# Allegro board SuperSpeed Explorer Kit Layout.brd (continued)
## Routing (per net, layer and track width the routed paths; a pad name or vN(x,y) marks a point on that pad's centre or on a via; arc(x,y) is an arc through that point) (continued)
DQ1: length 107.6
  TOP w0.183: R45.2 v2(51.3,39.51)
  L03_SIG1 w0.127: v2(51.3,39.51) 51.3,41.91 51.51,42.13 51.8,42.13 52.01,41.92 52.01,40.19 52.19,40.02 52.48,40.02 52.69,40.23 52.69,43.31 52.92,43.54 53.22,43.54 53.42,43.34 53.42,41.4 53.59,41.22 53.84,41.22 54.04,41.43 54.04,43.2 56.03,45.19 58.86,45.19 59.06,45.39 59.06,45.76 58.81,46 56.16,46 54.14,43.98 53.91,43.98 53.76,44.13 53.76,44.37 56.26,46.88 56.26,48.15 56.9,48.78 58.86,48.78 J6.36
  L06_SIG2 w0.127: v3(56.1,42.53) 56.03,42.53 55.6,42.97 55.6,44.05 56.58,45.03 60.74,45.03 61.84,46.14 66.61,46.14 67.52,45.23 74.93,45.23 75.18,45.48 75.18,46.29 74.69,46.78 67.83,46.78 67.5,47.11 67.5,47.83 67.78,48.12 73.43,48.12 74.08,48.76 74.08,51.28 73.79,51.58 73.23,51.58 73.1,51.45 73.1,50.52 72.89,50.31 72.53,50.31 72.3,50.53 72.3,51.49 72.04,51.75 64.44,51.75 64.11,51.42 64.11,49.45 63.7,49.05 61.7,49.05 61.47,49.28 61.47,51.96 61.09,52.34 59.18,52.34 58.93,52.08 58.93,50.31 59.12,50.12 J6.36
  BOTTOM w0.183: U5.B7 v3(56.1,42.53)
DQ2: length 110
  TOP w0.183: R27.2 v2(39.51,42.95)
  L06_SIG2 w0.127: v2(39.51,42.95) 38.94,43.52 36.21,43.52 33.5,46.24 31.97,46.24 30.99,47.22 30.99,50.41 31.78,51.2 56.58,51.2 J6.34 57.66,49 58,48.65 65.55,48.65 66.39,49.49 66.39,51.12 66.6,51.32 67.03,51.32 67.21,51.14 67.21,50.35 67.41,50.15 67.94,50.15 68.14,50.35 68.14,51.08 68.37,51.32 68.94,51.32 69.15,51.1 69.15,50.34 69.39,50.11 69.9,50.11 70.12,50.34 70.12,51.07 70.37,51.32 71.5,51.32 71.7,51.12 71.7,49.9 71.48,49.69 67.24,49.69 67.11,49.55 67.11,49.26 67.26,49.11 71.65,49.11 71.81,48.96 71.81,48.72 71.67,48.58 67.66,48.58 67.12,48.03 67.12,46.95 67.69,46.38 72.89,46.38 73.05,46.22 73.05,45.95 72.88,45.79 67.57,45.79 66.81,46.55 61.63,46.55 60.62,45.54 56.37,45.54 55.21,44.37 55.21,42.16 v3(56.1,41.26)
  BOTTOM w0.183: 56.58,40.78 v3(56.1,41.26)
DQ3: length 111.2
  TOP w0.183: R47.2 v2(51.18,36.72)
  L03_SIG1 w0.127: v2(51.18,36.72) 52.39,37.92 52.84,37.92 53.17,37.59 53.17,30.28 52.91,30.02 52.59,30.02 52.31,30.31 52.31,35.86 52.07,36.09 51.68,36.09 51.45,35.86 51.45,33.48 51.21,33.23 50.9,33.23 50.67,33.46 50.67,35.97 50.12,36.53 50.12,42.54 53.78,46.2 53.78,49.74 54.16,50.12 55.12,50.12
  L06_SIG2 w0.127: 55.12,50.12 55.01,50.22 54.03,50.22 53.72,49.92 53.72,49.22 54.1,48.85 55.93,48.85 56.32,48.45 56.32,46.84 56.59,46.57 60.3,46.57 60.48,46.39 60.48,46.13 60.33,45.98 55.15,45.98 54.82,45.65 54.82,40.88 55.07,40.63 56.5,40.63 56.73,40.86 56.73,43.21 57.12,43.6 60.54,43.6 62.27,45.34 66.25,45.34 68.78,42.81 71.25,42.81 71.71,42.34 71.71,40.58 71.47,40.33 71.05,40.33 70.84,40.55 70.84,42.01 70.65,42.19 67.41,42.19 66.94,42.66 66.94,43.64 65.67,44.91 62.51,44.91 60.75,43.15 58.12,43.15 57.85,42.89 57.85,40.84 57.52,40.51 57.12,40.51 56.61,39.99 v3(56.1,39.99)
  BOTTOM w0.183: U5.D7 v3(56.1,39.99)
DQ4: length 102
  TOP w0.183: v2(47.12,41.16) 45.85,41.16 45.1,40.41 R32.2
  L06_SIG2 w0.127: v3(56.1,38.72) 56.5,38.72 57.32,37.9 59.8,37.9 60.74,38.84 60.74,42.41 60.41,42.74 59.49,42.74 59.22,42.46 59.22,38.59 58.89,38.27 58.34,38.27 58.12,38.49 58.12,39.07 57.87,39.33 55.56,39.33 55.08,38.85 55.08,36.83 54.91,36.66 54.52,36.66 54.36,36.82 54.36,41.04 54.18,41.23 53.95,41.23 53.82,41.09 53.82,38.12 53.6,37.9 53.28,37.9 53.07,38.11 53.07,40.76 52.85,40.97 52.09,40.97 51.9,41.16 51.9,41.59 52.03,41.72 54.19,41.72 54.32,41.84 54.32,42.1 54.19,42.22 52.03,42.22 51.9,42.35 51.9,42.6 52.03,42.73 54.19,42.73 54.32,42.86 54.32,43.11 54.19,43.24 52.03,43.24 51.9,43.37 51.9,43.62 52.03,43.75 54.19,43.75 54.32,43.87 54.32,44.13 54.19,44.26 52.03,44.26 51.9,44.38 51.9,44.64 52.03,44.76 54.19,44.76 54.32,44.89 54.32,45.14 54.19,45.27 52.03,45.27 51.9,45.4 51.9,46.16 52.19,46.45 53.81,46.45 54.03,46.67 54.03,47.84 53.14,48.73 51.44,48.73 51.23,48.95 51.23,49.69 51.65,50.12 52.58,50.12
  BOTTOM w0.183: 56.58,38.24 v3(56.1,38.72) ; 52.58,50.12 53.39,50.12 54.63,48.87 58.28,48.87 58.85,49.43 58.85,50.66 58.28,51.22 51.68,51.22 51.33,50.87 51.33,49.6 50.37,48.64 46.74,48.64 46.23,48.13 46.23,42.05 v2(47.12,41.16)
DQ5: length 110.3
  TOP w0.183: R30.2 v2(47.42,42.95)
  L03_SIG1 w0.127: v2(47.42,42.95) 47.81,42.56 47.81,40.84 47.45,40.49 46.88,40.49 46.57,40.8 46.57,43.31 46.97,43.71 48.09,43.71 50.24,45.86 50.87,45.86 51.26,45.47 51.53,45.47 51.79,45.73 51.79,46.07 51.35,46.51 50.13,46.51 47.96,44.34 46.73,44.34 46.57,44.5 46.57,44.89 46.75,45.07 48.01,45.07 49.33,46.39 49.33,46.65 49.24,46.75 49,46.75 47.76,45.51 46.74,45.51 46.59,45.65 46.59,45.93 46.76,46.1 47.72,46.1 48.72,47.09 48.72,48.11 49.36,48.75 51.06,48.75 51.38,49.07 51.38,49.85 51.12,50.12 50.04,50.12
  L06_SIG2 w0.127: 50.04,50.12 49.02,50.12 48.71,49.82 48.71,46.67 51.5,43.89 51.5,40.9 52.65,39.74 52.65,37.95 54.45,36.16 55.25,36.16 55.55,36.45 55.55,37.65 55.79,37.89 56.46,37.89 56.72,37.63 56.72,37.2 56.95,36.97 60.21,36.97 60.46,37.22 60.46,37.6 61.19,38.33 61.19,42.61 61.35,42.77 61.52,42.77 61.68,42.61 61.68,38.29 61.9,38.07 62.59,38.07 62.85,38.33 62.85,39.04 63.07,39.26 63.9,39.26 64.17,39 64.17,38.15 63.97,37.95 63.17,37.95 62.89,37.68 62.89,37.04 63.09,36.85 63.88,36.85 64.17,36.56 64.17,33.28 64,33.11 63.27,33.11 63.14,32.98 63.14,32.3 63.28,32.16 63.95,32.16 64.19,31.92 64.19,30.91 63.92,30.64 63.07,30.64 62.78,30.93 62.78,36.33 62.47,36.63 61.79,36.63 61.64,36.78 61.64,37.42 61.46,37.61 61,37.61 60.84,37.45 60.84,36.86 60.62,36.63 56.41,36.63 56.1,36.95 v3(56.1,37.45)
  BOTTOM w0.183: U5.F7 v3(56.1,37.45)
DQ6: length 112.3
  TOP w0.183: R48.2 v2(49.53,35.32)
  L03_SIG1 w0.127: v2(49.53,35.32) 49.53,34.78 49.33,34.58 49.09,34.58 48.91,34.76 48.91,42.69 50.8,44.58 50.8,44.94 50.54,45.2 50.2,45.2 48.24,43.24 48.24,34.41 48.11,34.28 47.79,34.28 47.65,34.43 47.65,39.67 47.23,40.09 46.47,40.09 46.13,40.42 46.13,49.78 46.47,50.12 47.5,50.12
  L06_SIG2 w0.127: 47.5,50.12 46.48,50.12 46.12,49.76 46.12,46.97 45.72,46.56 44.88,46.56 44.42,46.1 41.81,46.1 41.49,45.78 41.49,45.52 41.85,45.16 44.27,45.16 45.22,46.11 48.66,46.11 51.08,43.7 51.08,40.57 52.26,39.39 52.26,37.77 54.11,35.92 54.11,33.37 54.27,33.21 54.45,33.21 54.63,33.38 54.63,35.62 54.75,35.74 55.04,35.74 55.15,35.63 55.15,32.23 55.28,32.09 55.48,32.09 55.63,32.24 55.63,35.09 55.9,35.36 57.57,35.36 57.82,35.11 57.82,33.33 58.01,33.14 60.66,33.14 61.81,31.98 62.15,31.98 62.36,32.2 62.36,32.46 61.69,33.14 61.69,35.6 61.53,35.76 61.28,35.76 61.14,35.62 61.14,33.69 61.01,33.57 60.72,33.57 60.56,33.72 60.56,35.15 60.27,35.44 59.72,35.44 59.44,35.17 59.44,34.38 59.23,34.17 58.36,34.17 58.18,34.35 58.18,35.49 57.95,35.72 56.56,35.72 v3(56.1,36.18)
  BOTTOM w0.183: 56.58,35.7 v3(56.1,36.18)
DQ7: length 99.8
  TOP w0.183: R34.2 v2(45.85,36.72)
  L06_SIG2 w0.127: 44.96,50.12 43.94,50.12 43.72,49.9 43.72,46.82 43.46,46.56 41.34,46.56 40.92,46.14 40.92,45.5 41.68,44.74 44.46,44.74 45.45,45.73 48.5,45.73 50.68,43.56 50.68,39.22 51.09,38.8 51.52,38.8 51.83,38.49 51.83,37.6 53.65,35.77 53.65,33.26 54.59,32.32 54.59,32.31 54.59,30 54.73,29.86 54.96,29.86 55.12,30.02 55.12,31.11 56.33,32.32 60.31,32.32 61.28,31.35 61.28,25.96 61.6,25.64 63.8,25.64 64.11,25.96 64.11,29.22 63.8,29.53 62.01,29.53 61.63,29.91 61.63,31.58 60.46,32.74 56.89,32.74 56.56,33.06 56.56,34.45 v3(56.1,34.91)
  BOTTOM w0.183: v2(45.85,36.72) 45.72,36.72 45.09,37.35 45.09,41.95 43.87,43.17 43.87,43.71 44.11,43.96 44.92,43.96 45.11,44.14 45.11,44.51 44.92,44.69 44.11,44.69 43.93,44.87 43.93,45.24 44.11,45.42 44.92,45.42 45.11,45.6 45.11,45.97 44.92,46.15 44.11,46.15 43.93,46.33 43.93,51.13 44.18,51.38 48.18,51.38 48.78,50.78 48.78,49.31 48.5,49.03 45.21,49.03 44.97,49.27 44.97,50.1 44.96,50.12 ; U5.H7 v3(56.1,34.91)
DQ8: length 113.3
  TOP w0.183: R49.2 v2(49.53,33.92)
  L03_SIG1 w0.127: v2(49.53,33.92) 49.18,33.57 47.64,33.57 47.17,34.03 47.17,38.33 46.87,38.63 46.11,38.63 45.75,38.99 45.75,40.26 45.75,40.26 45.75,45.99 45.35,46.38 45.1,46.38 44.87,46.16 44.87,42.64 44.67,42.44 44.43,42.44 44.23,42.63 44.23,46.12 44.06,46.3 43.8,46.3 43.65,46.15 43.65,43.83 43.43,43.62 43.23,43.62 43.04,43.81 43.04,45.6 42.85,45.79 38.8,45.79 38.61,45.98 38.61,46.29 38.84,46.52 43.37,46.52 43.67,46.81 43.67,48.84 42.42,50.08 J6.22
  L06_SIG2 w0.127: J6.22 41.53,50.12 41.06,49.66 41.06,46.99 40.58,46.51 37.16,46.51 36.94,46.29 36.94,46.03 37.13,45.83 39.98,45.83 41.53,44.28 44.7,44.28 45.74,45.32 48.31,45.32 50.25,43.38 50.25,38.45 53.2,35.51 53.2,33.15 54.17,32.18 54.17,29.84 54.59,29.42 55.36,29.42 55.56,29.63 55.56,30.43 55.86,30.73 57.74,30.73 58.01,30.47 58.01,29.64 58.29,29.36 59.23,29.36 59.46,29.6 59.46,30.6 59.65,30.79 60.09,30.79 60.36,30.51 60.36,24.49 60.48,24.37 60.77,24.37 60.89,24.49 60.89,31.17 60.15,31.9 56.59,31.9 v3(56.1,31.41)
  BOTTOM w0.183: U5.K7 v3(56.1,31.41)
DQ9: length 101.2
  TOP w0.183: R37.2 v2(45.85,32.53)
  L06_SIG2 w0.127: J6.20 39.88,49.27 39.52,48.91 36.77,48.91 36.25,48.39 36.25,46.04 36.89,45.4 39.74,45.4 41.27,43.87 44.9,43.87 45.95,44.91 48.11,44.91 49.87,43.15 49.87,36.59 50.42,36.04 50.42,30.58 50.59,30.41 51.02,30.41 51.18,30.57 51.18,35.91 51.32,36.04 51.57,36.04 51.69,35.92 51.69,30.54 51.82,30.41 52.07,30.41 52.2,30.54 52.2,35.37 52.32,35.49 52.57,35.49 52.71,35.35 52.71,30.54 52.84,30.41 53.09,30.41 53.22,30.54 53.22,32.04 53.35,32.17 53.6,32.17 53.72,32.05 53.72,29.51 54.53,28.71 55.24,28.71 56.1,29.57 v3(56.1,30.14)
  BOTTOM w0.183: v2(45.85,32.53) 45.85,32.98 46.02,33.16 47.09,33.16 47.37,33.44 47.37,35.73 47.02,36.08 45.47,36.08 44.53,37.02 44.53,41.62 43.45,42.7 43.45,43.4 43.1,43.75 42.06,43.75 41.85,43.95 41.85,44.39 42.04,44.58 43.19,44.58 43.45,44.83 43.45,45.21 43.27,45.39 42.09,45.39 41.82,45.65 41.82,46.17 42.05,46.39 43.03,46.39 43.45,46.81 43.45,50.82 42.98,51.29 40.17,51.29 39.88,51 J6.20 ; 56.58,30.62 v3(56.1,30.14)
DQ10: length 99
  TOP w0.183: R35.2 v2(45.85,35.32)
  L06_SIG2 w0.127: 37.34,50.12 36.29,50.12 35.86,49.68 35.86,45.8 36.7,44.95 39.52,44.95 41.01,43.47 45.17,43.47 46.21,44.5 47.85,44.5 49.46,42.89 49.46,36.32 50.04,35.74 50.04,30.27 50.35,29.95 52.74,29.95 54.46,28.23 57.4,28.23 57.83,27.8 57.83,26.5 59.25,25.08 59.25,22.74 59.52,22.46 61.42,22.46 61.94,22.98 63.75,22.98 63.99,23.22 63.99,24.06 63.76,24.29 61.6,24.29 60.98,23.67 60.14,23.67 59.79,24.02 59.79,25.67 59.26,26.2 59.26,28.09 59.01,28.33 58.11,28.33 57.9,28.54 57.9,28.98 57.56,29.32 56.54,29.32 v3(56.1,28.87)
  BOTTOM w0.183: v2(45.85,35.32) 45.47,35.32 44.02,36.77 44.02,40.63 41.35,43.3 41.35,44.38 41.12,44.61 40.04,44.61 39.8,44.85 39.8,45.29 40.08,45.58 40.86,45.58 41.39,46.1 41.39,48.54 40.89,49.04 36.49,49.04 36.01,49.52 36.01,50.96 36.35,51.3 38.34,51.3 38.63,51 38.63,50.28 38.39,50.03 37.42,50.03 37.34,50.12 ; U5.M7 v3(56.1,28.87)
DQ11: length 116.2
  TOP w0.183: R51.2 v2(49.53,31.13)
  L03_SIG1 w0.127: v2(49.53,31.13) 49.42,31.13 48.03,29.74 48.03,28.41 47.41,27.79 45.15,27.79 44.55,28.39 44.55,40.42 40.5,44.48 35.39,44.48 34.28,45.59 29.13,45.59 28.94,45.78 28.94,46.27 29.19,46.52 30.76,46.52 31.03,46.79 31.03,48.65 31.25,48.87 34.69,48.87 35.01,49.19 35.01,49.9 34.8,50.12
  L06_SIG2 w0.127: 34.8,50.12 34.03,50.12 33.66,49.74 33.66,47.26 36.51,44.4 39.42,44.4 40.77,43.05 45.38,43.05 46.32,43.99 47.75,43.99 48.93,42.81 48.93,29.46 49.22,29.17 51.5,29.17 51.68,28.98 51.68,28.77 51.5,28.58 49.1,28.58 48.93,28.41 48.93,26.89 49.1,26.71 49.36,26.71 49.55,26.9 49.55,27.98 49.69,28.12 50.65,28.12 50.78,27.99 50.78,26.59 50.9,26.46 51.16,26.46 51.29,26.59 51.29,27.95 51.42,28.09 51.85,28.09 51.97,27.97 51.97,26.03 52.1,25.9 52.35,25.9 52.48,26.03 52.48,27.47 52.61,27.6 52.86,27.6 52.99,27.47 52.99,26.03 53.11,25.9 53.37,25.9 53.49,26.03 53.49,27.47 53.62,27.6 53.88,27.6 54,27.47 54,26.03 54.13,25.9 54.38,25.9 54.51,26.03 54.51,27.47 54.64,27.6 54.89,27.6 55.02,27.47 55.02,26.03 55.15,25.9 55.4,25.9 55.53,26.03 55.53,26.62 55.77,26.86 56.42,26.86 56.58,27.03 56.58,27.45 56.43,27.6 56.1,27.6 v3(56.1,27.6)
  BOTTOM w0.183: 56.58,28.08 v3(56.1,27.6)
DQ12: length 102.2
  TOP w0.183: R36.2 v2(45.85,33.92)
  L06_SIG2 w0.127: v3(56.1,26.33) 56.65,26.33 57.11,25.87 57.57,25.87 58,25.44 58,23.27 57.74,23.02 56.94,23.02 56.64,23.32 56.64,25.27 56.39,25.52 52.72,25.52 52.52,25.33 52.52,24.98 52.73,24.77 53.72,24.77 53.9,24.59 53.9,24.22 53.7,24.01 52.35,24.01 51.36,23.03 51.09,23.03 50.94,23.18 50.94,23.35 51.6,24.01 51.6,24.19 51.44,24.36 51.2,24.36 50.47,23.63 48.81,23.63 48.52,23.92 48.52,24.4 48.77,24.65 50.99,24.65 51.15,24.81 51.15,25.14 50.96,25.34 48.87,25.34 48.52,25.69 48.52,42.62 47.62,43.53 46.43,43.53 45.54,42.63 40.62,42.63 39.23,44.02 36.26,44.02 33.27,47 33.27,49.1 32.26,50.12
  BOTTOM w0.183: U5.P7 v3(56.1,26.33) ; 32.26,50.12 32.23,50.09 30.99,50.09 30.78,50.29 30.78,51.06 31.04,51.32 33.19,51.32 33.44,51.08 33.44,49.47 33.82,49.09 35.68,49.09 36.11,48.65 40.51,48.65 40.91,48.26 40.91,46.81 40.21,46.12 39.4,46.12 39.08,45.8 39.08,44.94 43.51,40.5 43.51,36.26 v2(45.85,33.92)
DQ13: length 115
  TOP w0.183: R52.2 v2(49.53,29.73)
  L03_SIG1 w0.127: v2(49.53,29.73) 48.99,29.73 48.78,29.53 48.78,26.02 48.53,25.77 48.05,25.77 47.38,26.43 45.85,26.43 44.17,28.11 44.17,40.04 40.28,43.94 35.15,43.94 33.97,45.12 28.73,45.12 28.23,45.62 28.23,49.69 28.65,50.12 J6.12
  L06_SIG2 w0.127: v3(56.1,25.06) 55.72,25.06 55.34,24.68 55.34,23.72 55.13,23.5 52.51,23.5 51.6,22.59 50.59,22.59 49.93,23.25 49.33,23.25 48.84,22.76 48.4,22.76 48.08,23.08 48.08,41.57 46.94,42.72 46.32,42.72 45.78,42.18 37.56,42.18 36.82,41.44 35.75,41.44 35.43,41.75 35.43,43.77 33.66,45.54 23.52,45.54 23.33,45.74 23.33,46.17 23.58,46.42 28.14,46.42 28.41,46.69 28.41,49.71 28.82,50.12 J6.12
  BOTTOM w0.183: U5.R7 v3(56.1,25.06)
DQ14: length 119
  TOP w0.183: R38.2 v2(45.85,31.13)
  L06_SIG2 w0.127: v3(56.1,23.79) 55.3,22.99 52.67,22.99 51.81,22.13 48.18,22.13 47.63,22.68 47.63,41.42 46.87,42.18 46.47,42.18 46.06,41.76 41.11,41.76 40.26,40.91 35.34,40.91 34.92,41.33 34.92,43.74 33.54,45.12 21.71,45.12 21.36,45.47 21.36,46.17 21.71,46.51 22.95,46.51 23.25,46.81 23.25,48.47 23.69,48.91 25.97,48.91 27.18,50.12
  BOTTOM w0.183: U5.T7 v3(56.1,23.79) ; v2(45.85,31.13) 45.24,31.13 44.44,31.93 44.44,32.81 43.96,33.29 42.5,33.29 41.91,33.88 41.91,39.31 40.21,41.01 40.21,41.8 39.72,42.3 39.32,42.3 36.07,45.55 36.07,47.9 35.34,48.63 21.29,48.63 20.86,49.07 20.86,50.74 21.41,51.29 28.35,51.29 28.55,51.09 28.55,50.29 28.38,50.12 27.18,50.12 27.18,50.12
DQ15: length 107.4
  TOP w0.183: R19.2 v2(36.08,42.95)
  L03_SIG1 w0.127: 24.64,50.12 25.52,50.12 25.91,49.73 25.91,46.93 25.37,46.39 19.02,46.39 18.82,46.19 18.82,45.81 19,45.63 25.82,45.63 26.02,45.43 26.02,44.55 26.39,44.18 27.54,44.18 27.66,44.06 27.66,42.36 27.79,42.23 28.05,42.23 28.17,42.36 28.17,44.06 28.3,44.18 28.97,44.18 29.1,44.06 29.1,43.42 29.22,43.3 29.48,43.3 29.6,43.42 29.6,44.06 29.73,44.18 31.69,44.18 31.82,44.06 31.82,43.09 31.94,42.97 32.2,42.97 32.32,43.09 32.32,44.06 32.45,44.18 33.63,44.18 34.86,42.95 v2(36.08,42.95)
  L06_SIG2 w0.127: 24.64,50.12 24.64,50.18 23.5,51.32 21.69,51.32 20.84,50.47 20.84,45.33 21.42,44.74 33.38,44.74 34.54,43.57 34.54,41.12 35.14,40.53 40.51,40.53 41.29,41.31 45.8,41.31 47.15,39.96 47.15,22.4 47.92,21.63 52.1,21.63 53,22.52 v3(56.1,22.52)
  BOTTOM w0.183: U5.U7 v3(56.1,22.52)
DQ16: length 111.7
  TOP w0.183: J7.38 62.74,8.12 63.6,7.26 67.13,7.26 67.31,7.08 67.31,5.91 67.49,5.73 67.86,5.73 68.04,5.91 68.04,7.08 68.23,7.26 69.92,7.26 70.1,7.44 70.1,10.3 69.84,10.56 51.17,10.56 48.84,12.89 46.36,12.89 45.5,13.75 42.22,13.75 41.4,14.56 R29.2
  L06_SIG2 w0.127: J7.38 62.4,8.46 61.97,8.9 61.97,10.36 62.36,10.75 62.36,12.68 62.54,12.87 62.83,12.87 62.96,12.74 62.96,11.75 63.08,11.62 63.34,11.62 63.46,11.75 63.46,12.74 63.59,12.87 63.84,12.87 63.97,12.74 63.97,11.75 64.1,11.62 64.35,11.62 64.48,11.75 64.48,12.74 64.61,12.87 64.86,12.87 64.99,12.74 64.99,11.75 65.11,11.62 65.37,11.62 65.5,11.75 65.5,12.77 65.62,12.9 65.88,12.9 66,12.77 66,11.75 66.13,11.62 66.38,11.62 66.51,11.75 66.51,13.3 66.65,13.43 66.9,13.43 67.02,13.31 67.02,11.75 67.15,11.62 67.4,11.62 67.53,11.75 67.53,13.11 67.65,13.23 67.91,13.23 68.04,13.11 68.04,11.75 68.16,11.62 68.42,11.62 68.54,11.75 68.54,13.03 68.85,13.33 70.67,13.33 71.51,14.17 73.09,14.17 73.96,15.05 73.96,26.6 74.66,27.3 74.66,30.41 73.04,32.03 71.83,32.03 69.53,34.32 69.53,37.37 65.64,41.26 65.64,42.85 64.95,43.53 v3(64.84,43.53)
  BOTTOM w0.183: U5.A1 64.63,43.32 v3(64.84,43.53)
DQ17: length 113.6
  TOP w0.183: R31.2 v2(42.8,17.92)
  L06_SIG2 w0.127: J7.36 61.25,9.51 61.25,10.46 61.07,10.64 60.57,10.64 60.44,10.52 60.44,9.7 60.32,9.58 60.06,9.58 59.94,9.7 59.94,10.52 59.81,10.64 59.55,10.64 59.43,10.52 59.43,9.7 59.3,9.58 59.05,9.58 58.92,9.7 58.92,10.52 58.79,10.64 58.54,10.64 58.41,10.52 58.41,9.7 58.28,9.58 58.03,9.58 57.9,9.7 57.9,10.52 57.78,10.64 57.52,10.64 57.4,10.52 57.4,9.7 57.27,9.58 55.95,9.58 55.76,9.76 55.76,10.34 55.95,10.53 56.59,10.53 56.87,10.8 56.87,11.47 57.14,11.74 60.82,11.74 62.37,13.28 65.21,13.28 65.74,13.81 67.35,13.81 67.55,13.62 68.59,13.62 68.79,13.81 70.16,13.81 72.65,16.31 72.65,24.54 73.53,25.41 73.53,26.94 72.8,27.67 72.8,30.35 69.08,34.07 69.08,37.08 67.53,38.63 66.43,38.63 65.2,39.86 65.2,42.01 v3(64.68,42.53)
  BOTTOM w0.183: 64.2,42.05 v3(64.68,42.53) ; v2(42.8,17.92) 43.43,17.29 43.43,16.36 43.94,15.86 43.94,13.35 46.86,10.43 67.34,10.43 68.16,9.6 68.16,5.5 67.16,4.49 61.84,4.49 61.31,5.03 61.31,7.35 J7.36
DQ18: length 110.7
  TOP w0.183: R26.2 40.01,13.27 40.61,12.67 43.23,12.67 43.61,12.29 43.61,10.67 43.85,10.43 44.24,10.43 44.4,10.59 44.4,12.18 44.59,12.36 44.95,12.36 45.14,12.18 45.14,10.63 45.34,10.43 45.7,10.43 45.87,10.59 45.87,12.18 46.05,12.36 46.42,12.36 46.6,12.18 46.6,10.6 46.8,10.4 47.16,10.4 47.33,10.57 47.33,11.93 47.6,12.2 48.05,12.2 50.28,9.96 61.11,9.96 61.48,9.58 61.48,7.6 61.04,7.16 57.96,7.16 57.66,7.46 J7.34
  L06_SIG2 w0.127: v3(64.68,41.26) 63.86,42.09 63.86,43.57 64.34,44.06 65.04,44.06 66.02,43.07 66.02,41.53 70.03,37.52 70.03,35.12 72,33.15 73.12,33.15 74.52,31.75 74.52,31.14 75.13,30.54 75.13,26.96 74.36,26.2 74.36,25.1 74.68,24.78 74.68,21.09 74.36,20.77 74.36,19.65 74.68,19.33 74.68,16.59 74.36,16.27 74.36,15.15 74.68,14.83 74.68,14.54 73.83,13.69 72.59,13.69 72.19,13.28 72.19,12.41 70.29,10.51 64.1,10.51 63.77,10.19 63.77,9.79 64.05,9.52 66.66,9.52 67.14,9.04 67.14,7.87 66.69,7.43 58.69,7.43 J7.34
  BOTTOM w0.183: U5.C1 v3(64.68,41.26)
DQ19: length 118.9
  TOP w0.183: R25.2 v2(40.01,17.92)
  L03_SIG1 w0.127: 55.12,8.46 54.11,9.46 46.52,9.46 46.29,9.69 46.29,9.99 46.5,10.2 49.18,10.2 49.39,10.4 49.39,10.65 49.16,10.88 46.51,10.88 46.31,11.07 46.31,11.31 46.47,11.47 48.19,11.47 48.37,11.65 48.37,11.89 48.21,12.05 46.47,12.05 46.28,12.25 46.28,12.48 46.45,12.66 47.78,12.66 48,12.88 48,13.94 46.34,15.6 45.81,15.6 45.61,15.39 45.61,14.37 45.39,14.15 45.08,14.15 44.86,14.37 44.86,16.05 47.05,18.25 47.05,18.53 46.8,18.78 46.45,18.78 43.12,15.46 42.06,15.46 41.93,15.58 41.93,16.11 41.81,16.23 41.55,16.23 41.43,16.11 41.43,15.58 41.3,15.46 41.05,15.46 40.92,15.58 40.92,16.11 40.79,16.23 40.54,16.23 40.41,16.11 40.41,15.58 40.28,15.46 39.62,15.46 39.27,15.8 39.27,17.66 39.54,17.92 v2(40.01,17.92)
  L06_SIG2 w0.127: 55.12,8.46 55.12,8.21 56.32,7 68.07,7 75.06,13.98 75.06,14.99 74.74,15.31 74.74,16.12 75.06,16.43 75.06,19.49 74.74,19.81 74.74,20.62 75.06,20.93 75.06,25.17 75.51,25.62 75.51,30.7 74.98,31.23 74.98,32.18 72.47,34.69 71.7,34.69 70.5,35.88 70.5,39.61 69.43,40.68 67.93,40.68 66.45,42.16 66.45,43.33 65.32,44.46 63.37,44.46 62.86,43.96 62.86,41.03 63.37,40.53 64.15,40.53 v3(64.68,39.99)
  BOTTOM w0.183: 64.2,39.51 v3(64.68,39.99)
DQ20: length 116.9
  TOP w0.183: R28.2 v2(41.4,17.92)
  L06_SIG2 w0.127: v3(64.68,38.72) 65.27,38.13 65.27,37.02 65.44,36.86 65.78,36.86 65.94,37.02 65.94,38.02 66.08,38.17 66.39,38.17 66.52,38.03 66.52,32.7 66.85,32.37 67.55,32.37 67.86,32.68 67.86,36.92 68.12,37.18 68.38,37.18 68.65,36.91 68.65,33.83 68.96,33.52 68.96,33.34 68.47,32.86 68.47,32.68 68.65,32.5 68.83,32.5 69.32,32.98 69.5,32.98 69.68,32.8 69.68,32.62 69.19,32.14 69.19,31.96 69.37,31.78 69.55,31.78 70.02,32.25 70.23,32.25 70.35,32.13 70.35,31.91 69.86,31.43 69.86,31.23 70.01,31.08 70.22,31.08 70.7,31.56 70.91,31.56 71.12,31.36 71.12,30.25 70.41,29.53 70.41,28.19 70.65,27.95 71.75,27.95 72.27,27.42 72.27,16.53 70.05,14.31 68.75,14.31 68.44,14 67.71,14 67.4,14.31 65.58,14.31 64.98,13.7 62.18,13.7 60.66,12.19 56.31,12.19 52.58,8.46
  BOTTOM w0.183: U5.E1 v3(64.68,38.72) ; 52.58,8.46 53.66,7.37 58.3,7.37 59.02,8.1 59.02,8.76 59.79,9.53 60.61,9.53 61.59,8.55 61.59,8.02 62.29,7.32 63.67,7.32 64.06,7.71 64.06,9.68 63.74,9.99 43.95,9.99 43.38,10.57 43.38,11.44 43.56,11.62 44.26,11.62 44.43,11.79 44.43,12.15 44.24,12.35 43.56,12.35 43.38,12.52 43.38,15.56 42.16,16.78 42.16,17.56 41.81,17.92 v2(41.4,17.92)
DQ21: length 98.9
  TOP w0.183: R24.2 38.61,14.32 39.31,13.62 39.31,13.04 39.08,12.8 37.81,12.8 37.58,12.58 37.58,12.12 37.81,11.89 40.83,11.89 41.09,11.63 41.09,11.23 40.89,11.02 36.19,11.02 35.98,10.82 35.98,10.43 36.24,10.17 43.21,10.17 43.8,9.58 48.92,9.58 50.04,8.46
  L06_SIG2 w0.127: 50.04,8.46 50.95,8.46 51.19,8.23 51.19,7.35 50.92,7.08 48.93,7.08 48.65,7.35 48.65,9.56 49.14,10.05 51.87,10.05 52.92,11.1 53.1,11.1 53.66,10.54 53.84,10.54 54.02,10.72 54.02,10.9 53.46,11.46 53.46,11.64 53.64,11.82 53.82,11.82 54.4,11.24 54.56,11.24 54.74,11.42 54.74,11.62 54.18,12.18 54.18,12.36 54.36,12.54 54.54,12.54 55.11,11.97 55.27,11.97 55.45,12.15 55.45,12.35 54.9,12.9 54.9,13.08 55.48,13.65 56.41,13.65 56.54,13.53 56.54,12.91 56.67,12.78 56.92,12.78 57.04,12.91 57.04,13.53 57.17,13.65 57.42,13.65 57.55,13.53 57.55,12.98 57.69,12.84 57.94,12.84 58.06,12.96 58.06,13.53 58.19,13.65 58.44,13.65 58.57,13.53 58.57,12.97 58.7,12.83 58.96,12.83 59.08,12.95 59.08,13.53 59.2,13.65 61.49,13.65 62,14.16 63.3,14.16 64.75,15.61 67.2,15.61 67.58,15.24 67.58,14.67 67.87,14.38 68.28,14.38 68.63,14.73 69.81,14.73 70.74,15.66 70.74,17.03 71.75,18.05 71.75,26.09 69.96,27.88 69.96,30.44 68.49,31.92 66.6,31.92 65.96,32.56 65.96,35.72 64.68,37 v3(64.68,37.45)
  BOTTOM w0.183: 64.2,36.97 v3(64.68,37.45)
DQ22: length 101.9
  TOP w0.183: 47.5,8.46 47.96,8.92 48.46,8.92 49,8.39 49,7.36 48.69,7.05 43.99,7.05 43.55,7.48 43.55,8.97 42.98,9.54 34.1,9.54 33.85,9.79 33.85,10.08 34.1,10.33 35.27,10.33 35.42,10.48 35.42,10.88 35.24,11.06 33.81,11.06 33.06,11.81 33.06,12.78 33.66,13.38 36.82,13.38 37.21,13.77 R20.2
  L06_SIG2 w0.127: v3(64.68,36.18) 65.54,35.32 65.54,32.25 66.27,31.53 68.34,31.53 69.52,30.34 69.52,27.79 71.34,25.97 71.34,19.1 69.03,16.79 66.53,16.79 66.07,16.33 62.41,16.33 61.98,15.9 61.98,14.8 61.35,14.17 54.98,14.17 52.21,11.41 52.21,10.96 51.76,10.51 50.57,10.51 50.37,10.7 50.37,11.25 50.23,11.39 49.8,11.39 49.67,11.26 49.67,10.62 49.54,10.5 49.29,10.5 49.16,10.62 49.16,11.26 49.03,11.39 48.78,11.39 48.65,11.26 48.65,10.62 48.53,10.5 48.27,10.5 48.15,10.62 48.15,11.26 48.02,11.39 47.76,11.39 47.64,11.26 47.64,10.62 47.51,10.5 47.26,10.5 47.13,10.62 47.13,11.26 47,11.39 46.75,11.39 46.62,11.26 46.62,10.62 46.49,10.5 46.24,10.5 46.11,10.62 46.11,11.26 45.99,11.39 45.73,11.39 45.61,11.26 45.61,10.62 45.48,10.5 45.22,10.5 45.1,10.62 45.1,11.26 44.97,11.39 44.72,11.39 44.59,11.26 44.59,10.62 44.46,10.5 44.21,10.5 44.08,10.62 44.08,11.26 43.95,11.39 43.64,11.39 43.36,11.11 43.36,10.35 43.64,10.06 45.89,10.06 47.5,8.46
  BOTTOM w0.183: U5.G1 v3(64.68,36.18)
DQ23: length 99.3
  TOP w0.183: R23.2 v2(38.61,17.92)
  L03_SIG1 w0.127: 44.96,8.46 45.75,9.26 45.75,13.49 45.54,13.7 45.17,13.7 44.96,13.49 44.96,10.05 44.72,9.81 44.46,9.81 44.26,10.01 44.26,14.27 43.55,14.98 42.15,14.98 41.78,14.6 36.91,14.6 36.71,14.81 36.71,15.17 36.95,15.41 38.49,15.41 38.69,15.61 38.69,15.85 38.47,16.07 37.65,16.07 37.47,16.25 37.47,16.55 37.87,16.96 37.87,17.63 38.17,17.92 v2(38.61,17.92)
  L06_SIG2 w0.127: 44.96,8.46 44.96,9.34 44.62,9.68 42.14,9.68 41.01,10.81 36.3,10.81 36.13,10.98 36.13,11.5 36.3,11.66 41.23,11.66 41.8,11.09 42.27,11.09 42.97,11.8 52.05,11.8 56.67,16.41 57.82,16.41 58.32,16.92 65.75,16.92 66,17.17 68.87,17.17 70.96,19.26 70.96,25.81 69.13,27.64 69.13,29.12 67.12,31.12 66.06,31.12 65.15,32.04 65.15,34.44 v3(64.68,34.91)
  BOTTOM w0.183: U5.H1 v3(64.68,34.91)
DQ24: length 113.6
  TOP w0.183: v2(31.62,14.31) R13.2
  L03_SIG1 w0.127: J7.22 42.42,9.41 42.19,9.64 38.34,9.64 38.12,9.86 38.12,10.11 38.31,10.3 41.23,10.3 41.35,10.42 41.35,10.68 41.21,10.81 38.24,10.81 38.12,10.94 38.12,11.19 38.24,11.32 41.23,11.32 41.35,11.44 41.35,11.69 41.21,11.83 38.24,11.83 38.12,11.95 38.12,12.21 38.24,12.34 41.23,12.34 41.35,12.45 41.35,12.71 41.21,12.84 38.24,12.84 38.12,12.97 38.12,13.22 38.24,13.35 41.99,13.35 42.12,13.48 42.12,14.02 41.92,14.22 35.68,14.22 34.36,15.54 32.35,15.54 31.62,14.81 v2(31.62,14.31)
  L06_SIG2 w0.127: v3(64.68,31.41) 66.38,29.71 67.18,29.71 68.03,28.86 68.03,28.2 70.58,25.65 70.58,19.45 69.31,18.19 68.99,18.19 66.24,18.19 65.37,17.32 58,17.32 57.58,16.9 56.55,16.9 51.85,12.21 48.14,12.21 47.89,12.46 41.82,12.46 41.73,12.54 38.73,12.54 38.3,12.11 35.71,12.11 35.39,12.42 33.96,12.42 33.59,12.05 33.59,10.74 33.92,10.41 40.76,10.41 41.07,10.1 41.07,7.99 41.19,7.86 41.82,7.86 J7.22
  BOTTOM w0.183: 64.2,31.89 v3(64.68,31.41)
DQ25: length 98.3
  TOP w0.183: 35.81,15.11 35.81,14.14 35.51,13.84 32.47,13.84 31.5,12.87 27.64,12.87 27.21,12.44 27.21,11.3 27.56,10.95 28.28,10.95 28.77,11.44 31.24,11.44 33.42,9.26 33.42,7.66 33.89,7.19 39.4,7.19 39.88,7.67 J7.20
  L06_SIG2 w0.127: J7.20 39.88,9.58 39.46,9.99 31.81,9.99 30.35,11.44 30.35,12.05 30.79,12.49 31.03,12.49 31.38,12.14 31.38,11.98 31.7,11.66 32.15,11.66 32.47,11.98 32.47,12.43 32.47,12.44 32.47,12.6 32.6,12.73 33.7,12.73 33.81,12.84 35.04,12.84 35.58,13.38 41.43,13.38 41.98,12.84 48.25,12.84 48.38,12.72 50.65,12.72 51.92,13.98 52.88,13.98 56.19,17.29 57.33,17.29 57.77,17.73 65.23,17.73 66.08,18.57 69.15,18.57 70.2,19.61 70.2,23.87 67.84,26.23 67.84,26.98 v3(64.68,30.14)
  BOTTOM w0.183: U5.L1 v3(64.68,30.14)
DQ26: length 109.7
  TOP w0.183: 35.81,18.67 v2(35.81,17.92)
  L03_SIG1 w0.127: v2(35.81,17.92) 36.14,17.92 36.6,17.46 36.6,16.36 36.18,15.95 31.66,15.95 30.9,15.19 30.9,14.01 31.24,13.67 31.96,13.67 32.34,14.04 32.34,14.68 32.68,15.03 33.41,15.03 33.73,14.71 33.73,10.08 34.12,9.69 36.55,9.69 36.82,9.96 36.82,11.63 36.57,11.88 36.14,11.88 35.89,11.63 35.89,10.45 35.71,10.28 34.57,10.28 34.26,10.58 34.26,12.06 34.54,12.34 35.9,12.34 36.1,12.54 36.1,12.87 35.91,13.06 34.52,13.06 34.26,13.32 34.26,13.6 34.45,13.79 37.04,13.79 37.38,13.45 37.38,8.5 37.34,8.46
  L06_SIG2 w0.127: v3(64.68,28.87) 66.17,27.38 66.17,26.74 68,24.91 68,22.8 68.24,22.55 68.24,20.12 67.89,19.78 59.21,19.78 57.1,17.67 55.88,17.67 52.64,14.43 51.78,14.43 50.5,13.14 48.61,13.14 48.52,13.22 42.13,13.22 41.59,13.77 35.43,13.77 34.88,13.22 33.66,13.22 33.54,13.11 32.2,13.11 32.14,13.06 31.1,13.06 30.94,13.22 29.24,13.22 28.96,12.94 28.96,11.09 29.82,10.23 30.97,10.23 31.61,9.59 35.53,9.59 36.1,9.02 36.1,7.74 36.38,7.46 37.07,7.46 37.34,7.73 37.34,8.46
  BOTTOM w0.183: U5.M1 v3(64.68,28.87)
DQ27: length 117.5
  TOP w0.183: R15.2 v2(34.42,17.92)
  L06_SIG2 w0.127: 34.8,8.46 33.63,7.3 33.63,5.16 33.14,4.67 31.51,4.67 31,5.18 31,9.12 30.65,9.46 29.41,9.46 27.99,10.89 27.99,13.05 28.93,13.98 31.25,13.98 31.42,13.82 31.83,13.82 31.88,13.87 33.23,13.87 33.34,13.98 34.57,13.98 35.11,14.53 42.26,14.53 42.59,14.86 43,14.86 43.88,13.98 47.75,13.98 49.27,15.5 52.63,15.5 55.18,18.06 56.85,18.06 58.98,20.18 66.71,20.18 67.61,21.09 67.61,24.74 64.75,27.6 v3(64.68,27.6)
  BOTTOM w0.183: U5.N1 v3(64.68,27.6) ; v2(34.42,17.92) 34.42,19.23 34.6,19.41 35.11,19.41 35.29,19.23 35.29,16.72 35.76,16.25 38.98,16.25 39.26,16.52 40.6,16.52 41.15,15.98 41.15,15.49 40.88,15.22 36.27,15.22 36.03,14.99 36.03,14.73 36.27,14.49 40.9,14.49 41.08,14.31 41.08,13.94 40.9,13.76 37.56,13.76 37.39,13.59 37.39,13.22 37.59,13.03 40.9,13.03 41.08,12.84 41.08,12.48 40.9,12.3 37.66,12.3 37.47,12.1 37.47,11.74 37.64,11.56 40.9,11.56 41.08,11.38 41.08,11.02 40.9,10.83 35.61,10.83 34.8,10.02 34.8,8.46
DQ28: length 92.8
  TOP w0.183: R8.2 v2(27.43,14.34)
  L03_SIG1 w0.127: v2(27.43,14.34) 26.83,14.34 26.14,13.65 26.14,10.82 26.61,10.35 28.58,10.35 28.86,10.62 28.86,11.06 28.73,11.18 27.83,11.18 27.7,11.31 27.7,11.56 27.83,11.69 28.73,11.69 28.86,11.82 28.86,12.07 28.73,12.2 27.83,12.2 27.7,12.33 27.7,12.58 27.83,12.71 28.73,12.71 28.86,12.83 28.86,13.09 28.73,13.21 27.83,13.21 27.7,13.34 27.7,13.6 27.83,13.72 30.08,13.72 30.29,13.51 30.29,9.04 J7.12
  L06_SIG2 w0.127: J7.12 27.56,10.62 27.56,13.58 27.26,13.87 26.33,13.87 25.83,13.37 25.83,11.61 25.25,11.04 23.98,11.04 23.6,11.42 23.6,12.49 26.01,14.91 42.1,14.91 42.44,15.24 43.16,15.24 43.49,14.91 45.18,14.91 45.65,14.44 47.57,14.44 47.97,14.83 47.98,14.83 48.3,15.15 48.3,15.17 49.07,15.94 52.4,15.94 52.94,16.47 52.94,17.21 56.29,20.56 66.55,20.56 67.09,21.11 67.09,23.52 64.68,25.93 v3(64.68,26.33)
  BOTTOM w0.183: 64.2,26.81 v3(64.68,26.33)
DQ29: length 103.6
  TOP w0.183: R14.2 v2(33.02,17.92)
  L06_SIG2 w0.127: 27.18,8.46 27.18,13.15 26.89,13.43 26.54,13.43 26.22,13.11 26.22,9.99 25.84,9.61 23.94,9.61 22.97,10.59 22.97,12.51 23.75,13.3 23.75,15.07 24.04,15.36 42.02,15.36 42.28,15.62 43.32,15.62 43.58,15.36 46.21,15.36 47.3,16.45 51.38,16.45 53.72,18.8 53.72,19.88 54.97,21.13 65.56,21.13 66.49,22.06 66.49,23.25 v3(64.68,25.06)
  BOTTOM w0.183: v2(33.02,17.92) 33.02,18.48 31.85,19.65 25.27,19.65 25.03,19.41 25.03,19.12 25.2,18.95 27.76,18.95 28.22,18.49 28.22,16.91 28.58,16.55 28.58,16.17 28.35,15.94 27.47,15.94 27.23,15.71 27.23,15.36 27.48,15.12 28.55,15.12 28.93,14.74 28.93,10.16 28.67,9.9 28.37,9.9 28.11,10.17 28.11,13.49 27.85,13.75 27.49,13.75 27.18,13.44 27.18,8.46 ; U5.R1 v3(64.68,25.06)
DQ30: length 95.2
  TOP w0.183: R3.2 v2(24.64,17.92)
  L03_SIG1 w0.127: v2(24.64,17.92) 25.25,17.31 25.25,16.78 25.5,16.52 29.21,16.52 29.34,16.4 29.34,16.02 29.21,15.89 25.27,15.89 24.77,16.4 23.49,16.4 23.02,15.92 23.02,11.6 20.83,9.41 20.83,7.63 21.21,7.25 23.43,7.25 24.64,8.46
  L06_SIG2 w0.127: v3(64.68,23.79) 65.15,23.32 65.15,22.16 64.5,21.51 53.83,21.51 53.34,21.02 53.34,18.96 51.23,16.85 45.03,16.85 44.11,15.93 43.55,15.93 43.48,16 42.12,16 42.05,15.93 23.61,15.93 23.27,15.59 23.27,15.15 22.02,13.91 22.02,10.5 23.38,9.15 23.38,4.62 23.78,4.22 25.34,4.22 25.85,4.73 25.85,8.1 25.48,8.46 24.64,8.46
  BOTTOM w0.183: U5.T1 v3(64.68,23.79)
DQ31: length 102
  TOP w0.183: R7.2 v2(27.43,17.92)
  L06_SIG2 w0.127: v3(64.68,22.52) 64.05,21.89 53.62,21.89 52.96,21.23 52.96,19.11 51.14,17.29 44.86,17.29 44.03,16.46 23.51,16.46 22.94,17.03 19.43,17.03 18.97,16.57 18.97,9.56 18.39,8.98 18.39,7.91 18.82,7.48 18.82,6.72 18.39,6.29 18.39,5.36 18.87,4.87 20.43,4.87 20.94,5.38 20.94,7.3 22.1,8.46
  BOTTOM w0.183: U5.U1 v3(64.68,22.52) ; 22.1,8.46 22.1,7.53 20.91,6.34 20.91,4.33 21.32,3.91 24.84,3.91 25.07,4.15 25.07,4.48 24.75,4.8 23.74,4.8 23.28,5.26 23.28,10.76 23.84,11.32 24.87,11.32 25.19,11.64 25.19,12.24 24.77,12.66 24.22,12.66 23.94,12.94 23.94,13.49 24.19,13.74 24.94,13.74 25.23,14.03 25.23,14.81 25.01,15.04 24.27,15.04 23.94,15.36 23.94,17.97 24.48,18.51 26.85,18.51 v2(27.43,17.92)
FSLC0: length 10.8
  TOP w0.183: v1(32.96,31.15) 33.23,30.88 33.23,30.88 U2.E6 ; v1(30.56,28.75) 30.78,28.97 30.78,28.97 U2.B4 ; U2.B2 v1(30.56,27.15)
  L06_SIG2 w0.127: v1(30.56,27.15) 30.17,27.54 30.17,28.36 v1(30.56,28.75) 30.96,29.14 31.52,29.14 31.76,29.38 31.76,29.94 v1(32.96,31.15)
  BOTTOM w0.127: 30.99,24.97 30.99,26.17 30.97,26.19 30.97,26.74 v1(30.56,27.15)
  BOTTOM w0.183: 30.99,24.97 R76.2
GPIO45: length 81.1
  TOP w0.183: U2.F2 v1(34.56,27.15) ; SW2.A1 66.13,15.83 v2(65.16,14.86) 64.41,14.11 52.7,14.11 v2(51.82,15)
  L03_SIG1 w0.127: v1(34.56,27.15) 34.56,24.82 33.92,24.18 33.92,17.65 v2(34.42,17.16)
  L06_SIG2 w0.127: 32.26,8.46 32.19,8.46 30.81,9.85 29.57,9.85 28.45,10.97 28.45,12.97 29.08,13.6 31.09,13.6 31.26,13.44 31.99,13.44 32.04,13.49 33.38,13.49 33.5,13.6 34.72,13.6 35.27,14.15 41.75,14.15 42.29,13.6 47.93,13.6 49.33,15 v2(51.82,15)
  BOTTOM w0.183: v2(34.42,17.16) 34.42,14.75 33.27,13.6 32.26,13.6 31.35,12.7 31.35,9.37 32.26,8.46 ; v2(65.16,14.86) 66.01,15.71 70.92,15.71 71.37,15.25 R64.1 C40.1
GPIO57_I2S-MCLK_VIO3_SW: length 45.7
  TOP w0.183: R6.2 26.04,15.1 26.04,14.51 25.81,14.28 25.81,5.37 27.36,3.82 58.1,3.82 J7.35
I2C_SCL_FX3: length 117.8
  TOP w0.183: U2.D9 v1(32.16,33.55) ; U3.28 73.21,40.33 v2(74.3,41.42)
  L03_SIG1 w0.127: J6.40 68.47,50.12 74.49,44.11 74.49,43.23 74.79,42.93 74.79,41.91 v2(74.3,41.42) 73.53,40.65 65.66,40.65 65.28,40.27 65.28,33.61 65.02,33.35 65.02,32.78 66.16,31.64 66.16,30.49 67.93,28.72 67.93,21.62 67.42,21.11 67.42,10.4 66.94,9.92 51.66,9.92 48.39,13.19 48.39,17.51 v2(48.72,17.84)
  L06_SIG2 w0.127: v1(32.16,33.55) U2.D9 32.56,31.79 32.81,31.54 33.13,31.54 33.66,31.01 33.66,28.97 34.28,28.34 36.34,28.34 36.57,28.11 36.57,27.79 36.8,27.55 38.71,27.55 38.96,27.31 38.96,24.81 41.91,21.86 42.55,21.86 43.81,20.59 43.81,19.06 45.03,17.84 v2(48.72,17.84)
  BOTTOM w0.183: v2(48.72,17.84) 48.72,16.98 49.17,16.52 U6.6 51.7,16.52 53.22,15 R72.1
I2C_SDA_FX3: length 108.3
  TOP w0.183: v2(74.3,42.3) 72.71,40.72 U3.29 ; v2(51.59,18.56) 53.33,16.81 62.1,16.81 62.69,16.22 v2(62.69,15.71) ; U2.D10 v1(32.16,34.35)
  L03_SIG1 w0.127: J6.39 70.55,47.58 74.16,43.97 74.16,43.1 74.3,42.96 v2(74.3,42.3) 73.91,41.92 66.29,41.92 64.9,40.53 64.52,40.53 64.01,40.02 64.01,33.26 65.78,31.48 65.78,28.98 67.55,27.21 67.55,21.78 67.04,21.27 67.04,15.14 66.01,14.11 63.12,14.11 62.61,14.62 62.61,15.63 v2(62.69,15.71)
  L06_SIG2 w0.127: v1(32.16,34.35) 32.85,34.35 33.36,33.84 33.36,31.7 34.04,31.03 34.04,29.4 34.29,29.15 36.32,29.15 36.57,28.9 36.57,28.59 36.81,28.34 38.57,28.34 38.57,28.35 38.98,28.35 39.5,27.83 39.5,25.03 42.28,22.25 46.74,22.25 47.76,21.23 50.79,21.23 51.59,20.44 v2(51.59,18.56)
  BOTTOM w0.183: R71.1 53.33,17.81 52.95,18.19 51.96,18.19 v2(51.59,18.56) 50.83,17.79 U6.5
I2S_CLK: length 63.5
  TOP w0.183: R12.2 v2(31.62,17.92)
  L03_SIG1 w0.127: v2(31.62,17.92) 30.97,17.27 30.97,16.98 29.5,15.51 24.94,15.51 23.8,14.37 23.8,10.94 25.69,9.05 25.69,7.84 25.03,7.18 23.92,7.18 23.24,6.5 23.24,4.81 24.23,3.82 61.59,3.82 62.74,4.97 J7.37
I2S_SD: length 43.5
  TOP w0.183: J7.33 56.07,4.33 29.11,4.33 28.4,5.04 28.4,9.21 27.86,9.75 26.86,9.75 26.34,10.27 26.34,13.36 26.78,13.79 28.08,13.79 28.83,14.54 R10.2
I2S_WS: length 40.4
  TOP w0.183: 55.12,5.92 54.04,4.84 31.43,4.84 30.9,5.37 30.9,9.09 29.81,10.18 27.2,10.18 26.76,10.61 26.76,12.89 27.24,13.37 29.11,13.37 30.23,14.49 R11.2
INT_N_CTL15: length 45.8
  TOP w0.203: U2.L8 38.16,32.35 38.34,32.53 39.47,32.53 39.63,32.37 v1(39.63,32.37)
  BOTTOM w0.183: J7.3 20.95,7.32 20.95,9.41 23.49,11.95 23.49,18.7 24.63,19.84 24.65,19.85 25.01,20.21 33.48,20.21 33.89,20.63 33.89,21.06 34.2,21.37 36.72,21.37 37.73,22.38 38.04,22.38 38.07,22.41 39.79,22.41 41.78,24.4 41.78,29.48 39.63,31.63 v1(39.63,32.37)
PCLK: length 32.8
  TOP w0.183: R55.2 50.16,25.54 51,24.7 v2(51.79,24.7)
  L03_SIG1 w0.127: v2(51.79,24.7) 51.79,24.72 55.59,28.52 55.59,42.67 56.11,43.19 60.45,43.19 60.9,43.64 60.9,46.88 J6.35
PMODE_0: length 45
  TOP w0.183: v1(35.36,28.75) 35.14,28.97 U2.G4
  L03_SIG1 w0.127: J7.11 30.99,7.19 30.99,9.92 33.02,11.95 v2(33.02,14.36) ; v1(35.36,28.75) 34.96,28.34 34.4,28.34 34.16,28.1 34.16,26.2 33.52,25.56 33.52,17.66 v2(33.02,17.16)
  BOTTOM w0.183: J4.1 40.89,19.95 39.24,18.3 39.24,17.05 38.82,16.64 36.87,16.64 36.45,17.06 36.45,19.06 35.56,19.95 34.29,19.95 33.66,19.32 33.66,17.79 v2(33.02,17.16) v2(33.02,14.36)
PMODE_1: length 39.7
  TOP w0.183: U2.H4 v1(35.36,29.55) ; v2(37.13,20.97) 37.13,20.39 37.21,20.3 v2(37.21,17.92)
  L03_SIG1 w0.127: v2(37.13,20.97) 36.78,21.32 36.73,21.32 35.67,22.38 35.67,26.01 35.76,26.09 35.76,29.14 U2.H4 v1(35.36,29.55) ; 27.18,5.92 28.21,5.92 28.6,6.31 28.6,9.46 28.15,9.91 26.45,9.91 25.64,10.72 25.64,13.89 26.72,14.97 29.75,14.97 31.16,16.38 34.73,16.38 35.16,16.81 35.16,18.2 35.4,18.43 36.7,18.43 v2(37.21,17.92)
  BOTTOM w0.183: R73.2 v2(37.21,17.92)
PMODE_2: length 46
  TOP w0.183: v1(38.73,27.95) 38.73,28.57 38.37,28.94 U2.L4 ; v2(42.8,14.36) v2(42.8,17.16)
  L03_SIG1 w0.127: v2(42.8,14.36) 43.73,13.43 43.73,8.02 42.88,7.16 41.74,7.16 41.23,6.64 41.23,5.32 40.2,4.29 26.27,4.29 24.64,5.92 ; v1(38.73,27.95) 39.96,26.73 39.96,24.95 43.41,21.5 43.41,18.29 43.4,18.27 43.4,17.76 v2(42.8,17.16)
RESET_IN: length 31.3
  TOP w0.183: v1(31.36,29.55) 31.61,29.79 U2.C5 ; SW1.B1 13.5,40.5 13.51,40.51 R1.1 14.1,39.77 13.95,39.62 v2(13.95,39.1)
  L03_SIG1 w0.127: 30.18,29.95 30.96,29.95 v1(31.36,29.55)
  L03_SIG1 w0.254: v2(13.95,39.1) 13.95,37.79 15.48,36.26 17.78,36.26 20.5,33.54 23.98,33.54 27.23,30.29 29.4,30.29 29.74,29.95 30.18,29.95
  BOTTOM w0.127: 28.68,29.12 30.38,29.12 30.4,29.14 30.96,29.14 v1(31.36,29.55)
  BOTTOM w0.183: C72.1 27.37,29.97 28.21,29.12 28.68,29.12
SPI-MISO_UART-TX: length 95.3
  TOP w0.183: v2(65.9,40) 67.55,38.35 U3.2 ; R9.2 v2(28.83,17.92)
  L03_SIG1 w0.127: v2(65.9,40) 65.93,40 66.17,39.76 66.17,32.4 67.31,31.26 68.71,31.26 70.48,29.48 70.48,11.44 66.04,7 43.5,7 J7.21
  BOTTOM w0.183: v2(28.83,17.92) 29.64,18.73 30.44,18.73 30.97,18.21 30.97,5.49 31.68,4.77 41.27,4.77 J7.21
SPI-MOSI_UART-RX: length 109.7
  TOP w0.183: R4.2 v2(24.64,14.36) ; U3.30 72.21,40.18 71.99,40.4 71.5,40.4 71.12,40.78 v2(71.12,43.57)
  L03_SIG1 w0.127: J7.19 38.75,4.79 26.55,4.79 26.07,5.27 26.07,9.66 25.18,10.55 25.18,13.82 v2(24.64,14.36)
  L06_SIG2 w0.127: v2(71.12,43.57) 71.79,44.25 74.19,44.25 74.8,43.64 74.8,42.02 76.57,40.25 77.29,40.25 77.7,39.84 77.7,37.43 78.46,36.67 78.46,26 79.93,24.52 79.93,22.42 78.1,20.6 78.1,14.42 67.76,4.08 41.72,4.08 J7.19
SPI-SCK_UART-RTS: length 39.8
  TOP w0.183: R5.2 v2(26.04,17.92)
  BOTTOM w0.183: v2(26.04,17.92) 26.83,17.12 26.83,16.66 26.54,16.37 26.54,9.76 25.78,9 25.78,5.47 27.41,3.84 47.96,3.84 50.04,5.92
SPI-SSN_UART-CTS: length 81.4
  TOP w0.183: U2.C1 v1(31.36,26.35) ; v2(30.23,17.92) v2(30.23,20.84)
  L06_SIG2 w0.127: v2(30.23,20.84) 31.36,21.98 v1(31.36,26.35) ; v2(77.47,16.27) 77.47,14.5 67.43,4.46 46.42,4.46 44.96,5.92
  BOTTOM w0.183: v2(30.23,17.92) 29.7,17.4 29.7,16.66 30.31,16.05 30.31,10.64 28.65,8.99 28.65,5.08 29.44,4.29 43.33,4.29 44.96,5.92 ; v2(77.47,16.27) 78.1,16.27 78.22,16.38 R62.1
SS_DM: length 22.9
  TOP w0.165: U2.A10 arc(29.99,33.83) 29.8,33.79 23.9,33.79 arc(23.6,33.92) 23.47,34.22 23.47,34.55 arc(23.57,34.77) v2(23.79,34.87)
  BOTTOM w0.165: U9.6 14.96,35.91 arc(14.87,36.12) 14.66,36.21 14.47,36.21 arc(14.32,36.27) 14.26,36.42 14.26,36.75 arc(14.38,37.05) 14.68,37.17 15.26,37.17 arc(15.49,37.08) 15.59,36.84 15.59,36.82 arc(15.92,36.49) 16.25,36.82 16.25,36.84 arc(16.34,37.08) 16.58,37.17 16.88,37.17 arc(17.24,37.1) 17.54,36.9 20.7,33.74 arc(21.31,33.33) 22.04,33.19 22.6,33.19 arc(23.22,33.44) 23.47,34.06 23.47,34.55 arc(23.57,34.77) v2(23.79,34.87)
SS_DP: length 22.9
  TOP w0.165: U2.A9 arc(30,33.26) 29.8,33.3 23.9,33.3 arc(23.25,33.57) 22.98,34.22 22.98,34.55 arc(22.88,34.77) v2(22.66,34.87)
  BOTTOM w0.165: U9.4 13.06,35.91 arc(13.15,36.12) 13.36,36.21 13.55,36.21 arc(13.7,36.27) 13.76,36.42 13.76,36.75 arc(14.03,37.4) 14.68,37.67 16.88,37.67 arc(17.43,37.56) 17.89,37.25 21.05,34.09 arc(21.5,33.79) 22.04,33.68 22.6,33.68 arc(22.87,33.79) 22.98,34.06 22.98,34.55 arc(22.88,34.77) v2(22.66,34.87)
SS_RX_M: length 17.4
  TOP w0.165: v2(25.65,26.3) 25.65,26.33 arc(25.73,26.51) 25.91,26.59 26.29,26.59 arc(26.91,26.71) 27.43,27.06 28,27.64 28.36,27.99 arc(28.92,28.37) 29.59,28.5 29.91,28.5 arc(30,28.48) 30.09,28.43 U2.A3
  BOTTOM w0.165: J1.9 17.01,25.5 arc(17.04,25.68) 17.14,25.82 arc(17.29,25.92) 17.47,25.96 17.72,25.96 arc(18.39,26.24) 18.67,26.92 18.67,28.08 arc(18.83,28.47) 19.22,28.63 19.75,28.63 U8.6 U8.5 arc(20.79,28.62) 20.95,28.62 21.35,28.62 arc(21.72,28.55) 22.03,28.34 23.26,27.11 arc(23.83,26.72) 24.51,26.59 25.4,26.59 arc(25.58,26.51) 25.65,26.33 v2(25.65,26.3)
SS_RX_P: length 17.4
  TOP w0.165: U2.A4 30.08,29.06 arc(30,29.01) 29.92,29 29.59,29 arc(28.73,28.83) 28.01,28.34 27.65,27.99 27.08,27.41 arc(26.72,27.17) 26.29,27.08 25.91,27.08 arc(25.73,27.16) 25.65,27.34 v2(25.65,27.37)
  BOTTOM w0.165: v2(25.65,27.37) 25.65,27.34 arc(25.58,27.16) 25.4,27.08 24.51,27.08 arc(24.02,27.18) 23.61,27.46 22.38,28.69 arc(21.91,29.01) 21.35,29.12 20.95,29.12 arc(20.79,29.12) U8.4 U8.7 19.22,29.12 arc(18.48,28.82) 18.18,28.08 18.18,26.92 arc(18.04,26.59) 17.72,26.46 17.55,26.46 arc(17.17,26.61) 17.01,27 J1.8
SS_TX_M: length 11.1
  TOP w0.165: C8.2 25.13,30.85 arc(24.84,30.66) 24.51,30.6 24.38,30.6 arc(24.16,30.67) v2(24.01,30.86)
  BOTTOM w0.165: J1.5 17.01,33.69 arc(17.04,33.54) 17.12,33.4 17.14,33.39 arc(17.29,33.29) 17.47,33.25 17.83,33.25 arc(18.48,32.98) 18.75,32.33 18.75,31.02 arc(18.87,30.72) 19.17,30.6 U8.10 U8.1 arc(20.79,30.59) 20.95,30.59 23.75,30.59 arc(23.94,30.67) v2(24.01,30.86)
SS_TX_P: length 11.1
  TOP w0.165: C9.2 25.13,29.85 arc(24.84,30.03) 24.51,30.1 24.38,30.1 arc(24.16,30.03) v2(24.01,29.84)
  BOTTOM w0.165: J1.6 17.01,32.21 arc(17.17,32.6) 17.55,32.75 17.83,32.75 arc(18.13,32.63) 18.25,32.33 18.25,31.02 arc(18.52,30.37) 19.17,30.1 19.75,30.1 U8.9 U8.2 arc(20.79,30.09) 20.95,30.09 23.75,30.09 arc(23.93,30.02) v2(24.01,29.84)
SSDM: length 1.9
  BOTTOM w0.165: J1.2 14.96,30.9 U9.1
SSDP: length 1.9
  BOTTOM w0.165: J1.3 13.06,30.91 U9.3
U3RX_VDDQ: length 2.1
  TOP w0.203: U2.A2 29.57,27.55 v1(28.96,26.94)
  BOTTOM w0.508: v1(28.96,26.94) 28.94,26.92 C68.1
  vias: v2(24.64,23.38) v2(25.27,23.05)
U3TX_VDDQ: length 3.5
  TOP w0.183: v1(30.56,29.55) 30.95,29.95 U2.B5
  BOTTOM w0.305: C70.1 28.7,30.48 28.92,30.26 28.92,29.92 29.29,29.55 v1(30.56,29.55)
  vias: v2(22.99,25.16)
USB3_VBUS: length 25.8
  TOP w0.203: 33.66,35.04 U2.E11
  TOP w0.381: 33.86,35.79 33.86,35.24 33.66,35.04
  TOP w0.762: J6.3 19.56,45.63 20.62,44.57 26.77,44.57 27.32,44.02 C10.1 27.32,37.46 27.81,36.97 33.37,36.97 33.86,36.48 33.86,35.94 33.86,35.9 33.86,35.8 33.86,35.79
  vias: v2(1.22,36.97) v2(1.22,35.57) v2(1.22,34.18) v2(2.03,12.46) v2(2.16,11.19) v2(2.49,36.97) v2(2.49,35.57) v2(2.49,34.18) v2(3,32.65) v2(3,31.13) v2(3.68,12.59) v2(3.76,36.97) v2(3.76,35.57) v2(3.76,34.18) v2(3.81,11.19) v2(4.52,32.65) v2(4.52,31.13) v2(4.67,29.15) v2(5.03,36.97) v2(5.03,35.57) v2(5.03,34.18) v2(5.69,32.12) v2(5.74,30.16) v2(6.3,36.97) v2(6.3,35.57) v2(6.3,34.18) v2(7.57,36.97) v2(7.57,35.57) v2(7.57,34.18) v2(9.27,10.05) v2(9.37,11.65) v2(11.81,51.32) v2(11.81,50.18) v2(12.42,8.7) v2(12.42,7.56) v2(12.42,4.51) v2(12.95,51.32) v2(12.95,50.18) v2(12.95,49.04) v2(12.95,47.89) v2(13.94,8.7) v2(13.94,7.56) v2(13.94,6.03) v2(13.94,4.51) v2(14.07,51.32) v2(14.07,50.18) v2(14.07,49.04) v2(14.07,47.89)
V_BUS: length 2.6
  TOP w0.254: U3.19 76.08,36.35 v2(76.33,36.59)
  TOP w0.508: U4.5 v2(73.96,30.03)
  BOTTOM w0.508: v2(73.96,30.03) 73.9,29.98 C39.1
  vias: v2(76.07,23.76) v2(76.2,21.86) v2(77.34,23.64) v2(77.6,21.73) v2(78.23,22.67) v2(79.25,23.48)
VIO: length 70.7
  TOP w0.127: 36.16,35.15 v1(36.16,35.15)
  TOP w0.203: U2.E3 v1(33.76,27.95) ; U2.F1 v1(34.16,25.13)
  TOP w0.254: U2.H11 36.16,35.15 ; U2.L9 38.72,33.15 39.12,33.54 v1(39.88,33.54)
  TOP w0.508: 38.92,37.11 39.88,36.15 v1(39.88,33.54) ; 38.92,37.11 R21.2 ; 38.92,37.11 38.15,36.34 36.67,36.34 36.16,35.83 v1(36.16,35.15)
  TOP w0.762: TP4.1 74.61,13.41 70.17,13.41 v2(69.6,12.84)
  BOTTOM w0.508: C55.1 33.88,28.03 33.78,27.93 ; R74.1 v4(33.02,10.55) ; C56.1 33.78,27.93 ; 33.78,27.93 v1(33.76,27.95) ; R73.1 37.78,19.97 38.05,20.23 38.05,21.43 v2(38.1,21.48) ; C46.1 39.12,33.16 39.5,33.54 v1(39.88,33.54) ; C53.1 C52.1 35.55,24.79 35.2,25.13 v1(34.16,25.13)
  BOTTOM w0.635: v1(36.16,35.15) 36.16,36.03 C51.1 36.36,36.07 37.77,37.48 C48.1
  BOTTOM w0.762: v2(38.1,21.48) 38.35,21.73 48.77,21.73 50.04,20.46 51.3,20.46 52.13,19.63 55.06,19.63 61.85,12.84 v2(69.6,12.84) 71.31,12.84 R64.2
XTALIN: length 12.2
  TOP w0.183: U2.C6 31.61,30.9 31.61,30.9 v1(31.36,31.15) ; Y1.1 30.78,40.65 30.78,38.6 C11.1 v2(31.8,38.59)
  L06_SIG2 w0.127: v2(31.8,38.59) 31.05,37.84 31.05,35.11 30.38,34.44 30.38,32.75 30.97,32.16 30.97,31.54 v1(31.36,31.15)
XTALOUT: length 13.5
  TOP w0.183: Y1.3 33.53,42.07 33.81,41.78 C12.2 v2(32.87,38.59) ; v1(31.36,31.95) 31.56,31.75 U2.C7
  L06_SIG2 w0.127: v2(32.87,38.59) 33.15,38.32 33.15,37.61 32,36.46 32,35.57 31.77,35.34 31.77,32.36 v1(31.36,31.95)
N02063:
  vias: v2(10.11,31.84) v2(10.08,30.27) v2(11.15,31.03) v2(11.15,29.6) v2(11.15,28.54)
N16673785: length 4.1
  TOP w0.183: v2(20.32,37.99) 20.76,37.55 FB2.2
  TOP w0.203: v1(30.56,30.35) 30.8,30.59 30.81,30.59 U2.B6
  BOTTOM w0.381: C64.1 30.43,30.48 v1(30.56,30.35) 30.67,30.24 C59.1
N16678744: length 19.5
  TOP w0.183: R22.1 v2(37.85,41.65) ; U2.G5 34.78,30.13 v1(34.56,30.35)
  L03_SIG1 w0.127: v2(37.85,41.65) 37.53,41.97 35.58,41.97 33.95,40.34 33.95,38.09 32.57,36.72 32.57,34.99 32.33,34.74 32,34.74 31.77,34.51 31.77,33.39 32.01,33.14 32.34,33.14 33.14,32.34 34,32.34 34.17,32.18 34.17,31.77 34.4,31.54 34.73,31.54 34.96,31.31 34.96,30.74 v1(34.56,30.35)
N16678748: length 14.5
  TOP w0.183: R50.1 v2(46.61,32.53) ; U2.H8 35.94,32.53 35.94,32.53 v1(36.16,32.75)
  L06_SIG2 w0.127: v2(46.61,32.53) 45.9,33.24 42.07,33.24 40.39,34.92 39.18,34.92 38.8,34.55 38.14,34.55 37.93,34.76 37.6,34.76 37.37,34.52 37.37,34.2 37.13,33.95 36.81,33.95 36.56,33.7 36.56,33.14 v1(36.16,32.75)
N16678768: length 19
  TOP w0.183: U2.K5 37.53,29.78 v1(37.76,29.55) ; R43.1 v2(42.93,24.14)
  L03_SIG1 w0.127: v2(42.93,24.14) 45.06,24.14 45.21,24.3 45.21,24.78 45,24.99 44.35,24.99 44.22,25.12 44.22,26.81 44.09,26.94 43.84,26.94 43.71,26.81 43.71,25.12 43.58,24.99 41.39,24.99 41.03,25.35 41.03,28.22 40.31,28.94 38.37,28.94 v1(37.76,29.55)
N16678772: length 11.4
  TOP w0.183: v1(36.16,31.15) U2.H6 ; R42.1 v2(42.93,25.54)
  L03_SIG1 w0.127: v2(42.93,25.54) 41.58,26.89 41.58,28.33 40.43,29.48 38.74,29.48 37.47,30.75 36.55,30.75 36.16,31.14 v1(36.16,31.15)
N16678828: length 15.2
  TOP w0.183: R56.1 v2(46.61,24.14) ; v1(36.16,30.35) 36.38,30.13 U2.J5
  L06_SIG2 w0.127: v2(46.61,24.14) 45.97,24.78 42.85,24.78 41.2,26.43 41.2,27.66 38.92,29.94 36.78,29.94 36.37,30.35 v1(36.16,30.35)
N16678842: length 13.4
  TOP w0.183: R44.1 v2(42.93,22.75) ; U2.H5 v1(36.16,29.55)
  L03_SIG1 w0.127: v2(42.93,22.75) 40.36,25.31 40.36,27.73 39.74,28.35 37.61,28.35 37.36,28.59 37.36,29.71 37.16,29.91 36.52,29.91 v1(36.16,29.55)
N16678980: length 18.7
  TOP w0.183: R46.1 v2(46.61,38.11) ; v1(34.56,34.35) 34.35,34.14 34.35,34.14 U2.F10
  L06_SIG2 w0.127: v1(34.56,34.35) 34.56,34.53 34.18,34.91 34.18,36.41 35.09,37.33 36.23,37.33 37.59,38.69 37.59,39.16 37.94,39.51 41.91,39.51 42.42,40.02 44.7,40.02 v2(46.61,38.11)
N16679050: length 19.8
  TOP w0.183: U2.F9 34.37,33.36 34.37,33.36 v1(34.56,33.55) ; R45.1 v2(46.61,39.51)
  L06_SIG2 w0.127: v1(34.56,33.55) 34.16,33.95 34.16,34.51 33.79,34.87 33.79,36.57 34.93,37.71 35.98,37.71 37.08,38.81 37.08,39.19 37.78,39.89 41.75,39.89 42.26,40.4 45.72,40.4 v2(46.61,39.51)
N16679094: length 17.2
  TOP w0.183: v1(34.56,31.95) 34.33,31.72 34.33,31.72 U2.F7 ; R27.1 v2(39.53,41.65)
  L03_SIG1 w0.127: v1(34.56,31.95) 34.56,32.18 34.12,32.62 33.33,32.62 32.56,33.4 32.56,34.58 33.44,35.46 33.44,36.6 34.43,37.59 34.43,40.01 35.49,41.07 38.94,41.07 v2(39.53,41.65)
N16679146: length 16.1
  TOP w0.183: v1(35.36,34.35) 35.17,34.16 35.17,34.16 U2.G10 ; R47.1 v2(46.61,36.72)
  L06_SIG2 w0.127: v2(46.61,36.72) 45.72,37.61 45.46,37.61 44.41,38.65 38.91,38.65 38.25,37.99 37.54,37.99 35.77,36.22 35.77,35.72 35.36,35.31 v1(35.36,34.35)
N16679206: length 15
  TOP w0.183: v1(36.16,34.35) 35.96,34.14 35.96,34.14 U2.H10 ; R48.1 v2(46.61,35.32)
  L06_SIG2 w0.127: v2(46.61,35.32) 46.11,35.82 45.15,35.82 43.74,37.22 37.88,37.22 36.24,35.59 36.03,35.59 35.8,35.36 35.8,35.34 35.77,35.31 35.77,34.99 35.88,34.87 35.88,34.63 v1(36.16,34.35)
N16679210: length 17
  TOP w0.183: U2.F8 34.35,32.53 34.35,32.54 v1(34.56,32.75) ; R30.1 v2(41.66,40.78)
  L03_SIG1 w0.127: v2(41.66,40.78) 41.5,40.62 35.64,40.62 34.78,39.76 34.78,37.33 33.82,36.37 33.82,35.4 33.31,34.89 33.31,33.85 33.49,33.68 33.49,33.67 34.29,32.86 34.3,32.86 34.41,32.75 v1(34.56,32.75)
N16679214: length 12.8
  TOP w0.183: R32.1 v2(42.93,39.51) ; U2.G9 34.96,33.15 v1(35.36,33.55)
  L03_SIG1 w0.127: v2(42.93,39.51) 42.91,39.49 39.73,39.49 36.1,35.87 35.92,35.87 35.52,35.47 35.52,35.29 34.96,34.73 34.96,33.95 v1(35.36,33.55)
N16679250: length 10.3
  TOP w0.183: v1(36.16,33.55) 35.96,33.35 35.96,33.35 U2.H9 ; R34.1 v2(42.93,36.72)
  L03_SIG1 w0.127: v2(42.93,36.72) 38.47,36.72 37.36,35.61 37.36,34.9 37.2,34.74 36.79,34.74 36.57,34.52 36.57,33.95 v1(36.16,33.55)
N16679742: length 10
  TOP w0.183: R35.1 v2(42.93,35.32) ; v1(37.76,35.15) 37.51,34.9 37.51,34.9 U2.K11
  L06_SIG2 w0.127: v1(37.76,35.15) 37.76,35.89 38.23,36.36 41.22,36.36 41.41,36.17 41.41,34.63 41.69,34.35 42.08,34.35 42.34,34.62 42.34,35.11 42.55,35.32 v2(42.93,35.32)
N16679746: length 7.8
  TOP w0.183: R37.1 v2(42.93,32.53) ; U2.J9 36.74,33.33 36.74,33.33 v1(36.96,33.55)
  L03_SIG1 w0.127: v2(42.93,32.53) 42.33,33.12 39.7,33.12 39.67,33.15 37.36,33.15 v1(36.96,33.55)
N16679750: length 14.1
  TOP w0.183: R49.1 v2(46.61,33.92) ; v1(36.96,34.35) 36.75,34.13 36.75,34.13 U2.J10
  L06_SIG2 w0.127: v2(46.61,33.92) 45.72,34.81 44.86,34.81 43.64,36.03 42.85,36.03 42.12,36.76 37.99,36.76 37.37,36.14 37.37,35 36.96,34.59 v1(36.96,34.35)
N16679786: length 11.2
  TOP w0.183: R51.1 v2(46.61,31.13) ; v1(38.35,34.13) U2.L10
  L06_SIG2 w0.127: v2(46.61,31.13) 46.61,31.47 46.07,32.02 42.66,32.02 40.17,34.51 39.46,34.51 39.08,34.13 v1(38.35,34.13)
N16679852: length 12.4
  TOP w0.183: R52.1 v2(46.61,29.73) ; v1(37.76,33.55) 37.57,33.36 37.57,33.36 U2.K9
  L06_SIG2 w0.127: v2(46.61,29.73) 46.61,29.79 45.9,30.49 44.3,30.49 43.17,31.63 42.38,31.63 40.27,33.74 40.27,33.83 40.04,34.06 39.94,34.06 39.93,34.08 39.52,34.08 39,33.55 v1(37.76,33.55)
N16679856: length 6.9
  TOP w0.183: U2.K10 37.57,34.16 37.57,34.16 v1(37.76,34.35) ; R36.1 v2(42.93,33.92)
  L03_SIG1 w0.127: v2(42.93,33.92) 42.31,34.54 37.95,34.54 v1(37.76,34.35)
N16679876: length 18.4
  TOP w0.183: R19.1 v2(36.96,39.89) ; U2.G8 v1(35.36,32.75)
  L03_SIG1 w0.127: v1(35.36,32.75) 34.97,33.14 34.41,33.14 34.16,33.39 34.16,35.93 34.87,36.64 36.3,36.64 36.96,37.3 36.96,38.14 36.83,38.26 35.46,38.26 35.33,38.39 35.33,38.57 35.46,38.7 38.45,38.7 38.61,38.85 38.61,39.68 38.4,39.89 v2(36.96,39.89)
